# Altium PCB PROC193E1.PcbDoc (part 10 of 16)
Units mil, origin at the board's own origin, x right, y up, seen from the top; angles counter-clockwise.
Board outline 7700 x 2300 mil, 6 copper layers (Top Layer, GND 1, SIG 1, PWR, GND 2, Bottom Layer), stack 60.98 mil thick; 946 components, 667 nets, 9401 pads, 1730 vias.
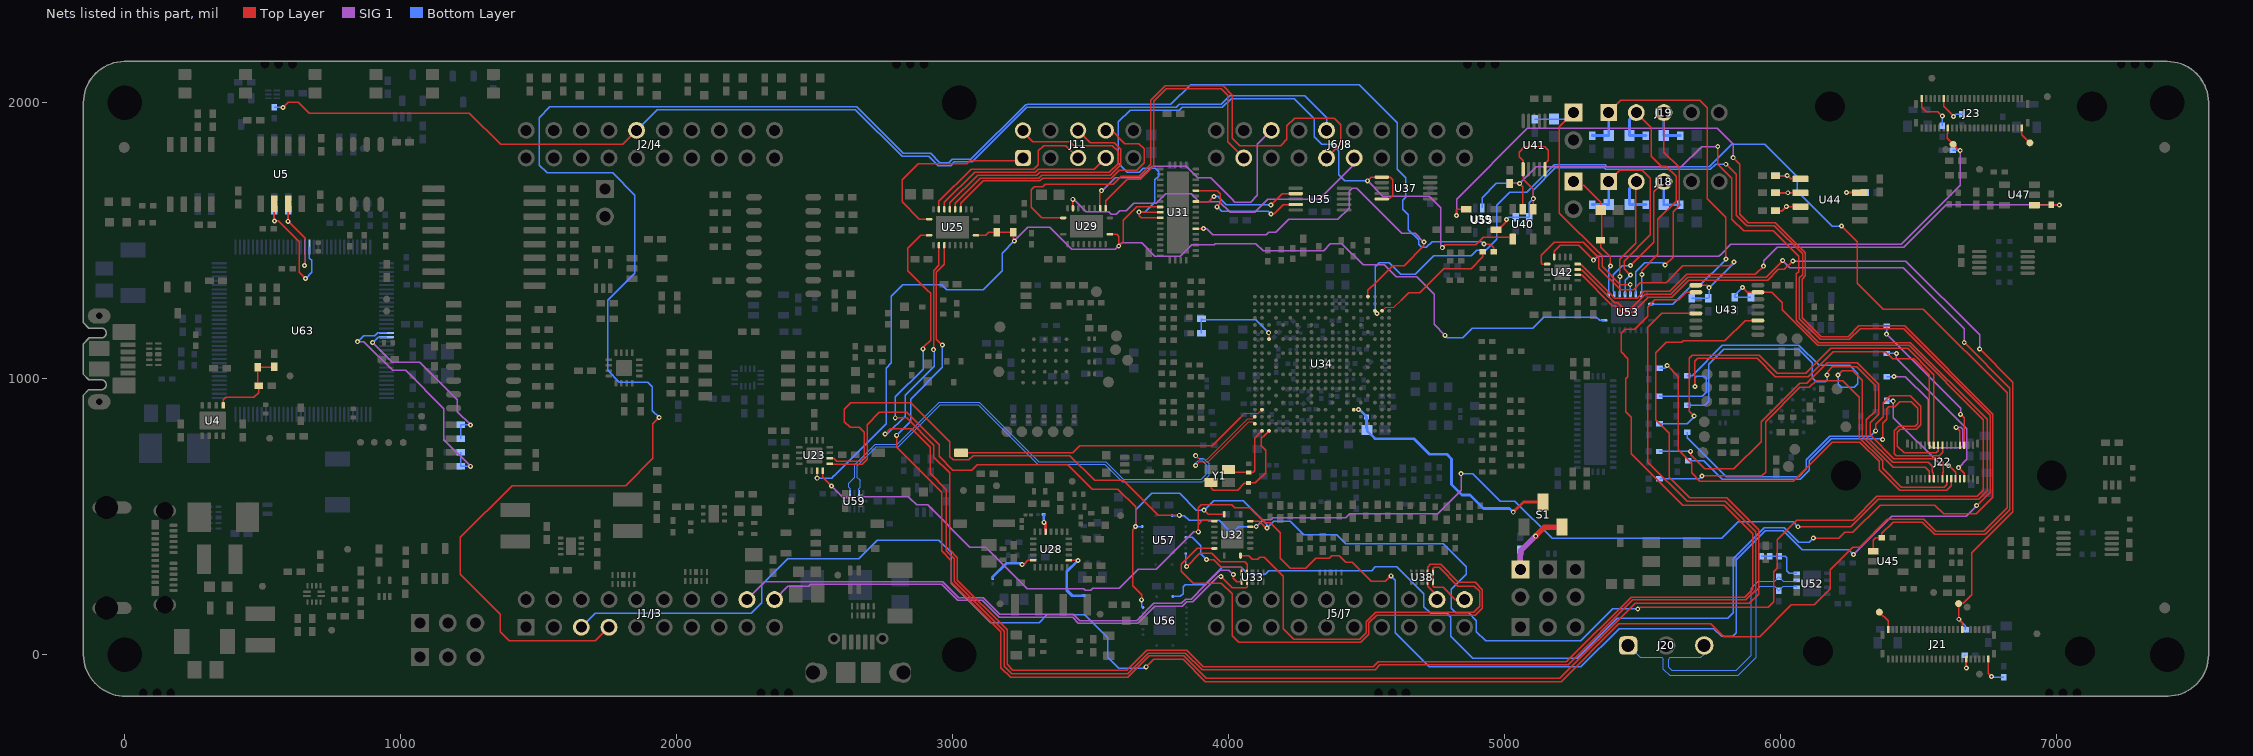
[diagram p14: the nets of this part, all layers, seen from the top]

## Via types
v1: diameter 18, hole 8, Top Layer to Bottom Layer, tented both sides, 1710 vias
v2: diameter 18, hole 8, Top Layer to Bottom Layer, tented top, 12 vias
v3: diameter 23.62, hole 11.81, Top Layer to Bottom Layer, tented both sides, 8 vias

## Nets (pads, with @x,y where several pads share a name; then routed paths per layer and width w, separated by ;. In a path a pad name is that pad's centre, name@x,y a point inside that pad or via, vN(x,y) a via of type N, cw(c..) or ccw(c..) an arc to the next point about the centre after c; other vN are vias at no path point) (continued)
AM261_UART3_RXD: J1/J3.3 U34.C18 | length 9757.5
  Top Layer w5.3: v1@3700.98,-43.56 3728.02,-16.52 3834.18,-16.52 3914.7,-97.04 5204.5,-97.04 5413.72,112.18 5746.9,112.18 5793.16,65.93 5923.9,65.93 6038.66,180.69 6121.12,180.69 6179.45,239.01 6179.45,308.99 6260.43,389.98 6284.37,389.98 6284.43,390.04 6285.17,390.04 6386.37,491.24 6517.78,491.24 6561.61,447.41 ; U34.C18@4529.52,1246.42 4536.77,1239.18 v1(4536.77,1236.43) ; v1(6220.27,1553.27) 6277.43,1496.1 6277.43,1346.74 6371.91,1252.26 6516.58,1252.26 6820.11,948.73 6820.11,532.79 6734.43,447.11 6561.93,447.11 6561.63,447.41
  Bottom Layer w5.3: J1/J3.3@1654.17,100 1704.25,150.07 2269.98,150.07 2308.09,188.19 2308.09,254.62 2402.06,348.58 2658.83,348.58 2725.97,415.72 2948.62,415.72 2951.81,412.53 2993.49,370.86 2994.67,369.67 2994.67,259.28 3137.05,116.89 3312.38,116.89 3341.09,145.6 3478.65,145.6 3562,62.25 3562,-8.66 3601.28,-47.93 3696.41,-47.93 v1(3700.78,-43.56) ; v1(4536.77,1236.43) 4536.77,1239.84 4530.72,1245.89 4530.72,1405.72 4546,1421 4581,1421 4623.53,1378.47 4675.47,1378.47 4742.37,1445.37 4877.82,1445.37 4897.53,1465.08 4931.26,1465.08 4971.37,1505.19 4971.37,1628.38 5018.5,1675.51 5080.2,1675.51 5179.33,1774.64 5364,1774.64 5369.72,1768.92 5740.92,1768.92 5821.55,1849.55 5940.96,1849.55 6059.24,1731.27 6059.24,1679.76 6185.73,1553.27 v1(6220.27,1553.27)
AM261_UART3_TXD: J1/J3.4 R172.1 | length 7527.5
  Top Layer w5.3: J1/J3.4@1754.17,100 1704.63,50.46 1393.79,50.46 1361.18,83.07 1361.18,146.72 1215.54,292.36 1215.54,425.29 1403.4,613.15 1814.26,613.15 1912.88,711.77 1912.88,836.52 v1(1936.3,859.93) ; v1(4925.1,1487.93) 4947,1487.93 4959.58,1475.35 4959.58,1461.04 R172.1@4959.95,1460.66
  Bottom Layer w5.3: v1(1936.3,859.93) 1911.69,884.54 1911.69,971.77 1895.44,988.02 1791.8,988.02 1749.41,1030.42 1749.41,1284.63 1848.05,1383.27 1848.05,1665.92 1767.49,1746.47 1529.89,1746.47 1501.97,1774.39 1500.76,1775.6 1500.76,1946.28 1540.47,1985.99 2651.41,1985.99 2820.61,1816.79 2919.91,1816.79 2953.34,1783.36 2985.96,1783.36 2998.43,1795.84 3065.89,1795.84 3263.79,1993.74 3269.46,1993.74 3269.76,1994.04 3790.19,1994.04 3862.3,2066.15 4472.11,2066.15 4610.2,1928.07 4610.2,1758.75 4641.15,1727.79 4641.15,1656.94 4630.24,1646.03 4630.24,1614.91 4650.95,1594.21 4650.95,1539.77 4687.33,1503.39 4687.33,1487.22 4698.76,1475.78 4714.94,1475.78 4736.33,1497.17 4915.65,1497.17 4924.89,1487.93 v1(4925.1,1487.93)
AM261_UART3_TXD_R: R172.2 U34.C19 | length 464.9
  Top Layer w3.94: U34.C19@4555.12,1246.42 4567.91,1259.22 4598.46,1259.22 4624.25,1285.01
  Top Layer w5.3: 4624.25,1285.01 4651.71,1312.47 4692.48,1312.47 4779.58,1399.57 4877.69,1399.57 4920.58,1442.47 R172.2@4920.58,1460.66
AM261_UART5_RXD: U31.27 U34.A17 | length 1326.9
  Top Layer w5.3: U31.27@3881.04,1543.92 3907.97,1543.92 v1(3908.26,1544.21) ; U34.A17@4503.93,1297.6 4503.93,1320.22 4532.14,1348.43 4593.86,1410.15 4635.64,1410.15 4706.85,1481.35 v1(4706.85,1495.3)
  SIG 1 w4.75: v1(3908.26,1544.21) 3919.5,1544.21 3941.52,1522.19 4136.2,1522.19 4144.42,1530.41 4169.24,1530.41 4216.59,1577.76 4395.17,1577.76 4435.97,1618.56 4435.97,1678.78 4447.4,1690.22 4464.23,1690.22 4627.25,1527.2 4674.96,1527.2 v1(4706.85,1495.3)
AM261_USB0_DRVVBUS: SW6.1 U34.U2 | length 1154.8
  Top Layer w3.94: 4043.66,860.5 4058.52,875.36 4107.28,875.36 U34.U2@4120.08,888.16
  Top Layer w5.3: SW6.1@3030.02,731.93 3435.18,731.93 3460.05,756.81 3939.74,756.81 3940.38,757.45 3940.61,757.45 4043.66,860.5
AM261_USB2.0_DM: U34.W1 U59.8 | length 1983.3
  Top Layer w4.2: v1(3879.98,685.43) 3893.38,698.83 3925.65,698.83 4013.45,786.63 4071.99,845.17 4086.29,845.17 U34.W1@4094.49,836.97
  Bottom Layer w4.2: U59.8@2628.07,584.08 2628.07,601.83 2623.63,606.26 2623.63,621.9 2639.3,637.57 2645.28,643.55 2645.28,689.12 2719.36,763.2 2799.34,763.2 2950.49,914.35 3095.5,914.35 3310.94,698.91 3554.05,698.91 3617.61,635.35 3900.16,635.35 3905.42,640.61 3919.06,654.25 3919.06,688.48 3903.77,703.77 3888.58,703.77 3881.73,696.92 3881.73,687.18 v1(3879.98,685.43)
AM261_USB2.0_DP: U34.V1 U59.10 | length 1983.8
  Top Layer w4.2: v1(3879.98,721.43) 3893.38,708.03 3921.84,708.03 4068.18,854.37 4086.29,854.37 U34.V1@4094.49,862.57
  Bottom Layer w4.2: U59.10@2659.56,584.08 2659.56,601.83 2664,606.26 2664,632.3 2658.73,637.57 2654.48,641.82 2654.48,685.31 2723.17,754 2803.15,754 2954.3,905.15 3091.69,905.15 3307.13,689.71 3550.24,689.71 3613.8,626.15 3903.97,626.15 3909.23,631.41 3928.26,650.44 3928.26,692.29 3907.58,712.97 3889.34,712.97 3880.88,721.43 v1(3879.98,721.43)
AM261_WARMRSTN: R325.1 R326.2 U34.G3 | length 339.7
  Top Layer w5.3: v1(4144.45,1166.96) 4145.67,1165.74 U34.G3@4145.67,1144.06
  Bottom Layer w5.3: R326.2@3900.83,1217.23 3903.64,1214.42 4097.14,1214.42 4144.45,1167.11 v1(4144.45,1166.96) ; R325.1@3901.01,1165.28 R326.2@3901.01,1217.06
AM261_XDS_I2C1_SCL: R381.2 R382.1 U63.82 | length 646.1
  SIG 1 w4.75: v1(898.28,1131.06) 969.75,1059.59 1068.02,1059.59 1204.06,923.55 1204.06,881.51 v1(1252.55,833.03)
  Bottom Layer w5.3: v1(898.28,1131.06) 917.96,1150.75 U63.82@948.65,1150.75 ; R381.2@1217.33,783.03 R382.1@1217.33,833.03 v1(1252.55,833.03)
AM261_XDS_I2C1_SDA: R379.1 R380.2 U63.81 | length 866.2
  SIG 1 w4.75: v1(843.5,1134.61) 866.26,1134.61 970.12,1030.75 1017.47,1030.75 1156.42,891.79 1156.42,779.54 v1(1252.93,683.03)
  Bottom Layer w5.3: v1(843.5,1134.61) 865.03,1156.14 905.95,1156.14 916.31,1166.5 U63.81@948.65,1166.5 ; R380.2@1217.33,733.03 R379.1@1217.33,683.03 v1(1252.93,683.03)
AM261_XTAL_XI: C88.2 U34.Y3 Y1.3 | length 407.1
  Top Layer w5.3: Y1.3@3935.33,614.43 3937.28,612.48 3937.28,602.85 3943.76,596.37 4032.37,596.37 4056.78,620.79 4069.55,620.79 C88.2@4071.47,622.7 4096.59,622.7 4133.79,659.91 4133.79,741.26 4118.29,756.75 4118.29,784.01 4130.13,795.85 U34.Y3@4145.67,811.38
AM261_XTAL_XO: C89.2 U34.Y2 Y1.1 | length 257.2
  Top Layer w5.3: Y1.1@3999.31,671.68 4010.35,660.64 C89.2@4072.36,660.64 4087.8,660.64 4093.97,666.81 4093.97,767.84 4093.97,785.28 U34.Y2@4120.08,811.38
BOOTMODE_XDS_I2C_SCL: R404.1 U5.3 U63.49 | length 359.4
  Top Layer w5.3: U5.3@591.82,1634.52 v1(591.82,1570.46) 653.63,1508.65 653.63,1413.16 v1(650.96,1410.49)
  Bottom Layer w5.3: v1(591.82,1570.46) R404.1@591.82,1610.89 ; v1(650.96,1410.49) 653.63,1413.16 653.63,1477.27 U63.49@653.37,1477.52
BOOTMODE_XDS_I2C_SDA: R406.1 U5.2 U63.50 | length 492.4
  Top Layer w5.3: U5.2@541.82,1634.52 541.82,1572.19 v1(541.97,1572.04) 556.6,1572.04 631.38,1497.26 631.38,1386.58 v1(654.75,1363.22)
  Bottom Layer w5.3: R406.1@541.82,1610.89 541.82,1572.19 v1(541.97,1572.04) ; v1(654.75,1363.22) 677.03,1385.5 677.03,1429.33 669.12,1437.24 U63.50@669.12,1477.52
BP_BO_MUX_EN: R90.1 R91.2 U23.7 U25.10 U29.10 U31.8 U53.10 | length 4407.9
  Top Layer w5.3: v1(2508.54,639.98) U23.7@2508.54,667.03 ; U25.10@3083.62,1519.54 3118.91,1519.54 3130.41,1531.05 R90.1@3160.08,1531.05 R91.2@3219.24,1531.05 3219.24,1506.56 3223.02,1502.78 v1(3223.02,1499.34) ; U29.10@3569.3,1523.67 3593.38,1523.67 3601.28,1515.77 v1(3601.28,1481.55) 3616.99,1497.26 3616.99,1573.56 3666.61,1623.18 3683.17,1623.18 3683.69,1622.66 U31.8@3751.12,1622.66
  SIG 1 w4.75: v1(3223.02,1499.34) 3272.25,1548.57 3351.96,1548.57 3430.91,1469.62 3589.35,1469.62 v1(3601.28,1481.55) 3611.81,1492.08 3684.93,1492.08 3732.58,1444.42 3824.52,1444.42 3865.4,1485.3 3947.22,1485.3 3951.79,1489.87 4098.55,1489.87 4124.04,1464.38 4343.18,1464.38 4368.33,1489.52 4409.94,1489.52 4486.89,1412.58 4563.75,1412.58 4606.32,1370.01 4680.3,1370.01 4743.68,1306.64 4743.68,1196.81 v1(4782.87,1157.62)
  Bottom Layer w5.3: v1(2508.54,639.98) 2560.85,639.98 2569.12,648.25 2569.68,648.25 2580.61,659.18 2580.61,659.73 2758.27,837.39 2758.27,1038.71 2776.95,1057.39 2776.95,1299.95 2817.81,1340.81 2960.08,1340.81 2977.79,1323.1 3111.03,1323.1 3179.44,1391.51 3179.44,1455.77 v1(3223.02,1499.34) ; v1(4782.87,1157.62) 4783.35,1157.62 4792.32,1148.64 4846.95,1148.64 4882.18,1183.88 5101.47,1183.88 5141.21,1223.61 5331.56,1223.61 5343.3,1211.87 U53.10@5360.84,1211.87
BP_BO_MUX_EN_N: R266.2 R267.1 U23.9 U32.1 U32.15 U43.15 U56.15 U57.15 | length 7424.7
  Top Layer w5.3: U23.9@2553.81,692.62 2555.41,691.02 2672.18,691.02 2689.46,708.31 2689.46,834.12 2733.55,878.2 2833.62,878.2 2950.32,761.5 2950.32,718.96 3000.7,668.58 3068.87,668.58 3088.78,688.48 3417.09,688.48 3505.21,600.36 3598.32,600.36 3662.05,536.64 v1(3662.05,464.41) 3651.54,453.9 3651.54,250.96 3684.05,218.45 v1(3684.05,199.17) ; v1(3910.51,523.8) 3925.01,509.3 U32.1@3983.28,509.3 ; U32.15@4077.76,483.71 4078.37,484.31 4110.52,484.31 4135.71,459.11 v1(4138.02,459.11) ; v1(5481.73,166.42) 5485.16,166.42 5490.42,171.68 5953.77,171.68 5975,192.91 5975,301.34 5987.2,313.54 5987.2,416.73 6057.87,487.4 6261.88,487.4 6348.25,573.77 6711.08,573.77 6734.1,596.79 6734.1,852.01 6465.06,1121.05 6133.73,1121.05 6004.36,1250.42 6004.36,1276.22 5967.11,1313.47 U43.15@5916.65,1313.47 5879.19,1313.47 v1(5861.48,1331.19)
  Bottom Layer w5.3: v1(3684.05,199.17) 3684.05,176.75 U56.15@3689.17,171.63 ; U57.15@3686.31,464.84 3686.09,464.63 3662.26,464.63 v1(3662.05,464.41) 3662.05,524.95 3721.7,584.6 3821.67,584.6 3882.46,523.8 v1(3910.51,523.8) 3945.7,559 4051.91,559 4138.02,472.89 v1(4138.02,459.11) 4162.69,483.78 4222.22,483.78 4271,435 4392,435 4424.43,402.57 4777.43,402.57 4860.78,319.22 4860.78,292.49 4806,237.71 4806,168 4822,152 4869,152 4897,124 4897,84 4930.41,50.59 5275.29,50.59 5391.12,166.42 v1(5481.73,166.42) ; v1(5861.48,1331.19) 5833.71,1303.42 R267.1@5833.71,1295.76 R266.2@5892.01,1295.76
BP_MCAN0_RX: U31.34 U35.9 | length 455.5
  Top Layer w5.3: U31.34@3881.04,1681.72 3958.46,1681.72 3969.66,1670.52 3969.66,1635.22 v1(3957.53,1623.1) ; v1(4153.42,1597.1) 4155.13,1598.82 4165.08,1598.82 4197.59,1631.32 U35.9@4242.38,1631.32
  Bottom Layer w5.3: v1(3957.53,1623.1) 3973.87,1606.76 4143.77,1606.76 v1(4153.42,1597.1)
BP_MCAN0_TX: U31.32 U35.7 | length 398.8
  Top Layer w5.3: U31.32@3881.04,1642.35 3927.35,1642.35 v1(3946,1661) ; v1(4152.12,1629.94) 4152.98,1629.94 4193.74,1670.69 U35.7@4242.38,1670.69
  Bottom Layer w5.3: v1(3946,1661) 3946.13,1660.87 3959.24,1660.87 3990.16,1629.94 v1(4152.12,1629.94)
BP_MUX_SW0_EXOR_SW1: U31.9 U31.10 U37.1 U37.5 U40.4 | length 2754.4
  Top Layer w5.3: U31.10@3751.12,1583.29 3683,1583.29 3675.08,1591.21 v1(3675.08,1603.66) 3675.76,1602.98 U31.9@3751.12,1602.98 ; v1(4502.64,1717.34) 4515.67,1730.37 4554.19,1730.37 U37.1@4554.27,1730.45 ; U37.5@4554.27,1651.71 4582.17,1651.71 4593.77,1663.32 4593.77,1721.87 4585.01,1730.63 U37.1@4554.44,1730.63 ; v1(4773.49,1475.03) 4784.22,1485.76 4895.33,1485.76 4922.72,1513.16 5021.2,1513.16 U40.4@5028.41,1505.94
  SIG 1 w4.75: v1(4502.64,1717.34) 4558.55,1661.43 4726.57,1661.43 4768.38,1619.62 4768.38,1483.72 4773.49,1478.61 v1(4773.49,1475.03)
  Bottom Layer w5.3: v1(3675.08,1603.66) 3695.07,1603.66 3731.79,1640.38 3731.79,1720.78 3745.4,1734.39 3745.4,1750.56 3733.96,1762 3689.15,1762 3676.37,1749.22 3631.83,1749.22 3600.01,1781.04 3600.01,1930.51 3642.33,1972.84 3821.07,1972.84 3831.67,1983.44 3977.17,1983.44 4008.38,2014.65 4237.98,2014.65 4309.65,1942.98 4309.65,1876.5 4336.15,1850 4375.38,1850 4398.57,1826.81 4398.57,1739.09 4420.32,1717.34 v1(4502.64,1717.34)
BP_MUX_SW0_N_AND_SW1: U39.4 U56.1 | length 6900.3
  Top Layer w5.3: v1(4825.38,1591.58) 4824.35,1592.61 4824.35,1611.18 4828.21,1615.04 U39.4@4860.29,1615.04 ; v1(5827.65,1801.13) 5851.89,1776.9 5851.89,1595.73 5882.1,1565.52 5980.72,1565.52 6089.15,1457.09 6089.15,1373.42 6077.24,1361.51 6077.24,1222.01 6146.34,1152.91 6244.61,1152.91 6283.15,1191.45 6449.33,1191.45 6768.61,872.17 6768.61,571.23 6708.46,511.08 6589.77,511.08 6558.12,542.74 6360.92,542.74 6261.54,443.36 6230.91,443.36 6210.67,423.12 v1(6117.93,423.12)
  SIG 1 w4.75: v1(4825.38,1591.58) 4825.38,1651.38 5082,1908 5770,1908 5827.65,1850.35 v1(5827.65,1801.13)
  Bottom Layer w5.3: U56.1@3797.44,211.39 3824.47,211.39 3834.75,221.66 3834.75,247.34 3841.91,254.51 3913.17,254.51 3975.96,317.3 4044.55,317.3 4070.45,291.41 4131.55,291.41 4145.14,305 4518.04,305 4531.16,318.13 4609.15,318.13 4706.85,220.42 4706.85,173.8 4730.82,149.83 4790.59,149.83 4804.27,136.15 4804.27,67.41 4883.83,-12.15 5263.21,-12.15 5407.85,132.5 5807.88,132.5 5827.3,151.91 5827.3,253.67 5827.9,254.27 5827.9,348.31 5940.33,460.74 6012.98,460.74 6065.06,408.66 6103.47,408.66 v1(6117.93,423.12)
BP_MUX_SW_S0: R175.2 R303.1 U23.10 U32.14 U40.2 U55.2 U57.1 | length 8116.8
  Top Layer w5.3: U23.10@2553.81,712.31 2554.21,711.91 2569.43,711.91 2579.46,701.89 2667.1,701.89 2678.38,713.17 2678.38,806.68 2660.93,824.14 2627.74,824.14 2606.67,845.21 2606.67,890.19 2630.11,913.64 2847.61,913.64 2989.78,771.47 2989.78,718.47 3001.8,706.45 3058.53,706.45 3073.52,721.43 3424.2,721.43 3513.48,632.15 3615.62,632.15 3615.75,632.02 3617.98,632.02 3744.68,505.32 v1(3820.64,505.32) ; U32.14@4077.76,464.02 4078.15,464.4 4099.12,464.4 v1(4099.5,464.79) ; R175.2@5017.69,1707.81 v1(5053.84,1707.81) 5065.82,1695.82 U40.2@5065.82,1614.21 ; v1(5771.53,1841.58) 5771.53,1777.57 5822.54,1726.56 5822.54,1578.54 5864.86,1536.21 5973.12,1536.21 6064.77,1444.56 6064.77,1388.19 6056.64,1380.07 6056.64,1212.7 6138,1131.35 6434.84,1131.35 6469.33,1131.35 6747.87,852.81 6747.87,594.34 6717,563.47 6352.52,563.47 6253.01,463.96 v1(6062.04,463.96)
  SIG 1 w4.75: v1(4099.5,464.79) 4124.09,489.39 4151.14,489.39 4158.57,496.82 4424.28,496.82 4438.34,510.88 4756.88,510.88 4841.82,595.82 v1(4841.82,656.33)
  SIG 1 w5.3: v1(5053.84,1707.81) 5113.83,1767.81 5639.45,1767.81 5713.23,1841.58 v1(5771.53,1841.58)
  Bottom Layer w5.3: U57.1@3794.57,504.6 v1@3819.93,504.6 ; v1(3820.64,505.32) v1@3819.93,504.6 ; v1(4099.5,464.79) 4036.12,464.79 4021.16,449.83 4002.29,449.83 3964.85,487.27 3856.01,487.27 3838.67,504.6 v1@3819.93,504.6 ; v1(4841.82,656.33) 4884.57,656.33 4983.93,556.97 5036.48,556.97 5171.45,422 5785.75,422 5845.09,481.34 6044.65,481.34 v1(6062.04,463.96) ; U55.2@4918.17,1619.01 4918.17,1656.11 4969.87,1707.81 R303.1@5017.69,1707.81 v1(5053.84,1707.81)
BP_MUX_SW_S1: R301.2 R302.1 U23.8 U32.2 U39.1 U40.1 U41.1 U41.5 | length 8942.2
  Top Layer w5.3: U23.8@2528.22,667.03 2528.22,643.98 v1(2560.77,611.42) ; v1(3889.58,445.68) 3889.37,445.9 3889.02,445.9 3889.02,471.66 ; U32.2@3947.84,483.71 3926.34,483.71 3922.99,487.06 3904.42,487.06 3889.02,471.66 ; v1(4587.26,286.14) 4567.01,265.88 4516.1,265.88 4446.7,335.28 4423.75,335.28 4412.34,346.7 4406.45,352.64 ccw(c4392.59,338.88) 4406.31,352.78 4400.68,358.41 4373.36,358.41 4364.42,349.47 4315.28,349.47 4278.62,312.81 4222.37,312.81 4185.93,349.25 4185.93,442.24 4150.51,477.66 4145.86,477.66 4145.75,477.76 4131.63,477.76 4076.2,533.19 4021.17,533.19 4010.37,543.99 3900.87,543.99 3889.02,532.14 3889.02,471.66 ; U39.1@4968.56,1540.23 4976.44,1540.23 5006,1569.79 v1(5006,1577.64) ; U40.1@5103.22,1614.21 v1(5103.22,1652.61) 5103.22,1686.04 5066.55,1722.71 5066.55,1789.84 5062.91,1793.48 5051.67,1804.72 5051.67,1821.28 5070.64,1840.25 5145.15,1840.25 5157.02,1828.39 5157.02,1791.4 5145.29,1779.68 U41.5@5145.29,1759.01 ; v1(5800.66,1777.31) 5802.2,1777.31 5838.29,1741.22 5838.29,1593.35 5875.27,1556.36 5876.69,1556.36 5877.83,1555.22 5976.46,1555.22 6078.85,1452.83 6078.85,1377.68 6066.94,1365.78 6066.94,1217.75 6142.07,1142.61 6248.88,1142.61 6287.41,1181.15 6445.06,1181.15 6758.31,867.91 6758.31,588.54 6710.4,540.63 v1(6709.9,540.63)
  SIG 1 w4.75: 2846.57,565.57 2869.15,543 2908.78,543 3062.03,389.75 3119.65,389.75 3270.39,239.01 3474.46,239.01 3479.7,233.78 3499.72,233.78 3507.52,241.58 3602.57,241.58 3671.58,310.59 3737.3,310.59 3872.35,445.64 3889.54,445.64 v1(3889.58,445.68) ; v1(6263.22,363.2) 6401.57,501.54 6671.31,501.54 6709.9,540.13 v1(6709.9,540.63)
  SIG 1 w5.3: v1(2560.77,611.42) 2599.2,573 2839.15,573 2846.57,565.57
  Bottom Layer w5.3: v1(4587.26,286.14) 4603.05,270.34 4603.05,80.62 4726.72,-43.05 5276.01,-43.05 5414.25,95.19 5757.74,95.19 5786.2,66.73 5825.94,66.73 5838.2,79 5838.2,344.05 5943.89,449.74 6008.84,449.74 6078.51,380.06 6246.36,380.06 v1(6263.22,363.2) ; v1(5006,1577.64) 5013.68,1585.32 R302.1@5039.74,1585.32 R301.2@5088.74,1585.32 5088.74,1638.13 v1(5103.22,1652.61) 5103.22,1683.97 5183.59,1764.34 5359.73,1764.34 5365.59,1758.48 5745.05,1758.48 5763.88,1777.31 v1(5800.66,1777.31)
BP_PORZ: J2/J4.16 J6/J8.56 R408.2 | length 4202.6
  Top Layer w5.3: v1(573.46,1983.42) 591.58,2001.54 628.24,2001.54 667.47,1962.31 1215.57,1962.31 1231.21,1962.31 1248.51,1962.31 1361.26,1849.56 1803.74,1849.56 J2/J4.16@1854.17,1900
  Bottom Layer w5.3: R408.2@541.97,1983.78 573.11,1983.78 v1(573.46,1983.42) ; J2/J4.16@1854.17,1900 1929.87,1975.69 2647.15,1975.69 2816.35,1806.49 2913.29,1806.49 2947.7,1772.09 2992.22,1772.09 3005.67,1785.54 3070.16,1785.54 3268.06,1983.44 3809.91,1983.44 3820.52,1994.04 3973.2,1994.04 4004.11,2024.95 4274.88,2024.95 4354.17,1945.66 J6/J8.56@4354.17,1900
BP_SPI2_CS0: J6/J8.58 U29.13 | length 987.7
  Top Layer w5.3: U29.13@3533.07,1628.97 3533.07,1618.95 U29.13@3533.87,1618.16 ; U29.13@3533.06,1628.98 3533.06,1672.74 3538.46,1678.14 v1(3538.46,1681.57)
  SIG 1 w4.75: v1(3538.46,1681.57) 3541.49,1681.57 3588.17,1728.25 3681.07,1728.25 3722.96,1770.13 3845.87,1770.13 3887.37,1728.63 3933.97,1728.63 4010.84,1651.76 4010.84,1651.7 4022.11,1640.42 4022.17,1640.42 4023.02,1640.42 4023.25,1640.19 4057.05,1640.19 4057.28,1640.42 4078.74,1640.42 4103.98,1665.65 4103.98,1849.81 J6/J8.58@4154.17,1900
CAN_STB: R257.1 R264.2 R265.1 U52.8 | length 181.5
  Bottom Layer w5.3: R265.1@5928.76,356.28 R264.2@5960.46,356.28 R257.1@5994.28,356.28 6016.9,356.28 6022.29,350.89 6022.29,304.28 6030.47,296.1 U52.8@6057.99,296.1
CANA_N: J20.1 R261.2 U52.6 | length 967.9
  Bottom Layer w3.8: J20.1@5446.96,33.86 5490.35,-9.53 5568.65,-9.53 5574.94,-15.82 5574.94,-52.72 5597.07,-74.85 5845.72,-74.85 5910.85,-9.72 5910.85,232.82 5926.34,248.31 5977.51,248.31 R261.2@5993.11,232.71 6008.71,248.31 6054.59,248.31 U52.6@6057.99,244.92
CANA_P: J20.3 R262.2 U52.7 | length 955.8
  Bottom Layer w3.8: J20.3@5722.55,33.86 5722.55,2.58 5710.44,-9.53 5600.34,-9.53 5593.74,-16.13 5593.74,-44.93 5604.86,-56.05 5837.93,-56.05 5892.05,-1.93 5892.05,240.61 5918.55,267.11 5977.51,267.11 R262.2@5993.11,282.71 6008.71,267.11 6054.59,267.11 U52.7@6057.99,270.51
CPSW/ICSS_BRD_CONN_DET1: J21.36 R234.1 TP50.1 U42.2 | length 2961.2
  Top Layer w5.3: U42.2@5263.64,1376.37 5263.91,1376.1 5279.38,1376.1 5390.04,1265.44 5399.59,1265.44 5423.63,1241.4 5465.89,1241.4 5520.44,1295.95 5605.46,1295.95 5666.98,1357.46 5952.9,1357.46 5991.49,1396.06 6013.2,1396.06 v1(6043.54,1426.39) ; J21.36@6656.78,91.39 6656.78,116.9 6644.15,129.53 TP50.1@6644.15,185.3 6645.7,186.86 6660.91,186.86 6679.45,205.39 6692.05,218 6692.05,369.75 6840.71,518.41 6840.71,988.23 v1(6720.46,1108.48)
  SIG 1 w5.3: v1(6043.54,1426.39) 6452.86,1426.39 6720.46,1158.8 v1(6720.46,1108.48)
  Bottom Layer w5.3: v1(6644.87,128.8) 6668.37,105.31 6668.37,91.42 R234.1@6669.17,90.62
CPSW/ICSS_BRD_CONN_DET2: J23.36 R237.1 TP49.1 U42.8 | length 1894.5
  Top Layer w5.3: U42.8@5178.99,1441.33 5178.99,1462.99 5200,1484 5267.49,1484 5321.53,1429.96 v1(5321.53,1429.88) ; J23.36@6605.69,1908.44 6605.69,1890.55 6602.79,1887.65 6602.79,1870.91 TP49.1@6624.15,1849.55 6646.7,1827 v1(6650,1827)
  SIG 1 w4.75: v1(5321.53,1429.88) 5335.99,1444.34 5775.64,1444.34 5779.56,1448.26 5779.76,1448.26 5818.51,1487.01 6435.69,1487.01 6650,1701.31 v1(6650,1827)
  Bottom Layer w5.3: R237.1@6622.33,1828.78 6648.22,1828.78 v1(6650,1827)
DAC_EXT_VREF: C157.1 J12.1 S1.3 | length 312.8
  Top Layer w20: v1(5111.94,429.89) 5111.94,431.17 5143.7,462.93 S1.3@5207.56,462.93
  SIG 1 w20: J12.1@5056.57,309.25 5056.57,375.81 5110.65,429.89 v1(5111.94,429.89)
  Bottom Layer w20: J12.1@5056.57,309.25 5056.57,365.5 5058.1,363.98
DAC_OUT/ADC0_AIN6: J1/J3.29 U33.1 U33.10 U57.4 | length 2293.6
  Top Layer w5.3: v1(3919.71,344.91) 3944.99,344.91 3971.9,318.01 4041.65,318.01 4046.55,313.1 U33.10@4046.55,297.78 U33.1@4046.55,264.9 4029.31,264.9 4016.33,277.88 v1(4016.33,291.12)
  SIG 1 w4.75: J1/J3.29@2254.17,200 2318.64,264.46 2964.06,264.46 3021.37,207.15 3110.23,207.15 3169.74,147.64 3435.99,147.64 3459.5,124.12 3665.83,124.12 3727.65,185.94 3827.94,185.94 3843.8,201.8 3864.13,201.8 3889.22,226.88 3889.22,228.84 3967.52,307.14 4000.31,307.14 v1(4016.33,291.12)
  Bottom Layer w5.3: U57.4@3843.79,425.47 3867.7,425.47 3898.47,394.7 3898.47,366.16 v1(3919.71,344.91)
DAC_OUT/ADC1_AIN6: J1/J3.30 U33.2 U33.9 U57.7 | length 2268
  Top Layer w5.3: v1(3847.27,319.45) 3895.14,367.32 3937.35,367.32 3968.17,336.5 4058.52,336.5 4066.23,328.79 U33.9@4066.23,297.78 U33.2@4066.23,264.9 4066.23,245.45 4063.13,242.34 4012.48,242.34 v1(3970.96,283.87)
  SIG 1 w4.75: J1/J3.30@2354.17,200 2402.35,248.17 2478.86,248.17 2485.4,254.71 2960.02,254.71 3017.33,197.4 3106.19,197.4 3167.89,135.7 3433.74,135.7 3455.07,114.38 3669.87,114.38 3731.69,176.19 3831.98,176.19 3847.84,192.05 3870.21,192.05 3962.02,283.87 v1(3970.96,283.87)
  Bottom Layer w5.3: U57.7@3843.79,366.41 3843.79,328.91 3844.84,327.85 3844.84,321.88 v1(3847.27,319.45)
DAC_OUT/PR1_PRU0_GPIO6/ADC2_AIN3: J5/J7.69 U32.7 U38.2 U38.9 | length 1969.9
  Top Layer w5.3: U32.7@3947.84,385.28 3885.71,385.28 3879.3,378.87 3879.08,378.87 3827.75,327.54 3827.75,303.43 3871.61,259.56 3972.85,259.56 4011.9,220.5 4011.9,69.18 4035.16,45.92 4474.01,45.92 4478.13,45.92 4507.42,75.21 4507.42,115.85 4535.69,144.13 4893.64,144.13 4919.01,169.49 4919.01,236.48 4892.25,263.24 4832.15,263.24 4767.1,328.29 4730.66,328.29 4719.99,317.63 U38.2@4719.99,297.78 U38.9@4719.99,264.9 4719.99,249.13 4754.17,214.96 J5/J7.69@4754.17,200
DAC_OUT/PR1_PRU1_GPIO5/ADC2_AIN6: J5/J7.70 U32.9 U38.1 U38.10 | length 1640.3
  Top Layer w5.3: U32.9@4042.33,359.69 4071.8,359.69 4085.13,346.36 4104.99,346.36 4112.29,353.66 4128.75,353.66 4197.9,284.52 4197.9,93.66 4235.34,56.22 4473.86,56.22 4497.12,79.47 4497.12,120.12 4531.91,154.91 4887.29,154.91 4908.37,175.99 4908.37,229.35 4888.74,248.98 4829.02,248.98 4761.65,316.35 4743.98,316.35 4739.68,312.05 U38.1@4739.68,297.78 U38.10@4739.68,264.9 4739.68,249.66 4745.04,244.3 4776.52,244.3 4820.83,200 J5/J7.70@4854.17,200
DAC_VREF: C168.1 C171.1 S1.2 U34.U15 | length 939.1
  Top Layer w5.3: U34.U15@4452.75,888.16 4453.04,888.45 4470.01,888.45 v1(4470.3,888.73)
  Top Layer w10: v1(5030.62,516.78) 5067.33,553.48 S1.2@5138.66,553.48
  Bottom Layer w10: v1(4470.3,888.73) 4471.83,887.2 4475.14,887.2 4494.69,867.66 4494.69,864.8 4497.95,861.53 C171.1@4498.74,861.53 4498.74,822.22 4501.23,819.73 C168.1@4501.23,814.75 4501.23,810.9 4529.13,783 4670.27,783 4726.77,726.51 4790.22,726.51 4807.34,709.38 4807.34,617.53 4845.43,579.44 4873.26,579.44 4922.72,529.98 5017.42,529.98 v1(5030.62,516.78)
EEPROM_A0: R200.2 R260.2 U44.1 | length 138
  Top Layer w5.3: R200.2@5981.07,1736.2 6022.36,1736.2 v1(6023.05,1736.89) 6035.89,1724.05 U44.1@6071.17,1724.05
  Bottom Layer w5.3: R260.2@5981.07,1736.2 6022.36,1736.2 v1(6023.05,1736.89)
EEPROM_A1: R202.2 R259.2 U44.2 | length 134.3
  Top Layer w5.3: R202.2@5981.07,1674.05 v1(6025.32,1674.05) U44.2@6071.17,1674.05
  Bottom Layer w5.3: R259.2@5981.07,1674.05 v1(6025.32,1674.05)
EEPROM_A2: R201.2 R258.2 U44.3 | length 142.5
  Top Layer w5.3: R201.2@5981.07,1609.41 6006.15,1609.41 6019.81,1623.07 v1(6019.81,1624.58) ; v1@6020.56,1623.83 6070.95,1623.83 U44.3@6071.17,1624.05
  Bottom Layer w5.3: R258.2@5981.07,1609.41 6006.15,1609.41 6019.81,1623.07 v1(6019.81,1624.58)
EEPROM_WP: R246.1 U44.7 | length 115.3
  Top Layer w5.3: v1(6237.78,1675.15) 6238.89,1674.05 U44.7@6285.74,1674.05
  Bottom Layer w5.3: v1(6237.78,1675.15) 6237.93,1675 R246.1@6304.65,1675
EPWM5_B: J6/J8.79 U29.12 | length 1035.2
  Top Layer w5.3: U29.12@3553.55,1618.16 3553.55,1644.97 3631.99,1723.41 3679.2,1723.41 3727.56,1771.78 3727.56,2004.71 3774.13,2051.27 3971.87,2051.27 3995.33,2027.81 3995.33,1858.84 J6/J8.79@4054.17,1800
EPWM7_A: J6/J8.76 U29.20 | length 2014.2
  Top Layer w5.3: U29.20@3400.01,1582.73 3322.75,1582.73 3283.86,1621.62 3283.86,1685.86 3294.52,1696.52 3325.3,1696.52 3334.17,1705.39 3582.24,1705.39 3582.75,1705.9 3582.96,1705.9 3585.21,1708.15 3611.08,1734.01 3674.81,1734.01 3717.26,1776.47 3717.26,2008.97 3717.44,2009.15 3717.44,2009.57 3769.74,2061.87 3978.99,2061.87 4013.14,2027.73 4013.14,1871.65 4040,1844.78 4187.91,1844.78 4210.46,1867.33 4210.46,1916.62 4238.34,1944.49 4382.14,1944.49 4405.81,1920.83 4405.81,1851.64 J6/J8.76@4354.17,1800
EPWM7_B: J6/J8.75 U29.18 | length 1228
  Top Layer w5.3: v1(3434.8,1650.39) 3435.48,1649.71 U29.18@3435.48,1618.19
  SIG 1 w4.75: v1(3434.8,1650.39) 3438.39,1650.39 3443.13,1645.64 3443.36,1645.64 3484,1605 3565,1605 3574,1596 3593,1596 3605.74,1608.74 3629.04,1608.74 3656.44,1636.14 3736.27,1636.14 3771.32,1671.2 3863.66,1671.2 3892.51,1642.35 3966.09,1642.35 4004.77,1603.66 4094.06,1603.66 4141.41,1651.01 4327.65,1651.01 4454.17,1777.53 J6/J8.75@4454.17,1800
EQEP0_A: C153.1 J19.1 R299.1 U53.20 | length 1445.8
  Top Layer w5.3: J19.1@5376.52,1964.55 5420.76,2008.8 5707.03,2008.8 5732.87,1982.95 5732.87,1652.02 5799.88,1585.01 5799.88,1435.47 v1(5801.75,1433.61)
  Bottom Layer w5.3: U53.20@5530.13,1270.93 5609.04,1270.93 5671.33,1333.22 5701.35,1333.22 v1(5801.75,1433.61)
  Bottom Layer w10: R299.1@5316.52,1881.05 C153.1@5376.52,1881.05 J19.1@5376.52,1964.55
EQEP0_B: C151.1 J19.2 R297.1 U53.18 | length 934.1
  Top Layer w5.3: J19.2@5476.52,1964.55 5531.04,1910.02 5531.04,1806.77 5567.61,1770.21 5583.67,1770.21 5620.84,1733.04 5620.84,1643.37 5554.94,1577.48 5554.94,1546.26 5554.94,1451.51 5495.62,1392.19 5495.62,1379.09 v1(5496.36,1378.35)
  Bottom Layer w5.3: U53.18@5494.7,1306.36 5495.49,1307.16 5495.49,1377.47 v1(5496.36,1378.35)
  Bottom Layer w10: J19.2@5476.52,1964.55 5451.52,1939.55 C151.1@5451.52,1881.04 R297.1@5511.52,1881.04
EQEP0_INDEX: C149.1 J19.3 R281.1 U53.17 | length 944
  Top Layer w5.3: J19.3@5576.52,1964.55 5576.52,1821.48 5631.44,1766.56 5631.44,1627.76 5609.46,1605.79 5609.46,1441.2 v1(5581.02,1412.76)
  Bottom Layer w5.3: U53.17@5475.01,1306.36 5475.01,1388.68 5506.8,1420.47 5571.57,1420.47 5579.27,1412.76 v1(5581.02,1412.76)
  Bottom Layer w10: J19.3@5576.52,1964.55 5575.69,1963.72 C149.1@5575.69,1881.04 R281.1@5635.69,1881.04
EQEP0_STROBE: C155.1 J16.1 R300.1 U53.16 | length 958.3
  Top Layer w5.3: J16.1@5248.63,1964.55 5197.86,1913.78 5197.86,1599.84 5352.59,1445.11 5352.59,1406.97 5418.17,1341.39 v1@5454.17,1341.39
  Bottom Layer w5.3: R300.1@5107.66,1939.9 5177.38,1939.9 C155.1@5178.34,1940.86 5224.94,1940.86 J16.1@5248.63,1964.55 ; v1(5454.54,1341.76) 5455.29,1341.02 U53.16@5455.33,1306.36 U53.16@5455.33,1306.36
EQEP1_A: C152.1 J18.1 R298.1 U53.15 | length 800.4
  Top Layer w5.3: J18.1@5376.52,1714.55 5417.22,1755.25 5459.18,1755.25 5459.52,1755.58 5498.47,1755.58 5527.75,1726.31 5527.75,1521.5 5432.73,1426.48 5432.73,1398.27 v1(5455,1376)
  Bottom Layer w5.3: U53.15@5435.64,1306.36 5435.64,1356.64 v1(5455,1376)
  Bottom Layer w10: R298.1@5316.52,1631.05 C152.1@5376.52,1631.05 J18.1@5376.52,1714.55
EQEP1_B: C150.1 J18.2 R296.1 U53.14 | length 587.3
  Top Layer w5.3: v1(5416.82,1370.73) 5416.82,1433.51 5474.54,1491.22 5474.54,1712.57 J18.2@5476.52,1714.55
  Bottom Layer w5.3: U53.14@5415.96,1306.36 5415.73,1306.59 5415.73,1369.63 v1(5416.82,1370.73)
  Bottom Layer w10: J18.2@5476.52,1714.55 5451.52,1689.55 C150.1@5451.52,1631.04 R296.1@5511.52,1631.04
EQEP1_INDEX: C148.1 J18.3 R280.1 U53.13 | length 646.7
  Top Layer w5.3: v1(5455,1410) 5540,1495 5540,1550.42 5540,1678.03 J18.3@5576.52,1714.55
  Bottom Layer w5.3: U53.13@5396.27,1306.36 5396.27,1314.57 5392.89,1317.95 5392.89,1377.19 5425.7,1410 v1(5455,1410)
  Bottom Layer w10: J18.3@5576.52,1714.55 5575.69,1713.72 C148.1@5575.69,1631.04 R280.1@5635.69,1631.04
EQEP1_STROBE: C110.1 J15.1 R192.1 U53.12 | length 485.1
  Top Layer w5.3: J15.1@5248.63,1714.55 5261.14,1702.04 5285.96,1702.04 5347.44,1640.56 C110.1@5347.44,1611.36 5351.54,1607.25 5351.54,1505.82 R192.1@5347.07,1501.35 5347.27,1501.15 5347.27,1477.27 5382.64,1441.9 v1(5382.64,1408.84)
  Bottom Layer w5.3: U53.12@5376.59,1306.36 5375.8,1307.16 5375.8,1399.39 5382.64,1406.23 v1(5382.64,1408.84)
ETH0_CPSW2_RST: R209.1 U42.3 U45.1 | length 2987.6
  Top Layer w5.3: U42.3@5263.64,1396.06 5264.27,1395.42 5279.02,1395.42 5398.7,1275.74 5409.26,1275.74 5432.58,1252.42 5455.3,1252.42 5509.13,1306.25 5601.19,1306.25 5662.71,1367.76 5947.06,1367.76 6006.75,1427.45 v1(6006.75,1428.12) ; U45.1@6334.74,375.59 6334.74,415.49 6343.25,424 R209.1@6366.26,424 6366.26,439.69 6407.5,480.92 6513.13,480.92 6557.54,436.51 6740.88,436.51 6830.41,526.04 6830.41,966.04 v1(6664.63,1131.82)
  SIG 1 w5.3: v1(6006.75,1428.12) 6032.1,1402.77 6443.82,1402.77 6664.63,1181.97 v1(6664.63,1131.82)
ETH1_CPSW1_RST: R221.1 U42.4 U47.1 | length 2039.5
  Top Layer w5.3: U42.4@5263.64,1415.74 5265.71,1413.67 5276.31,1413.67 5398.57,1291.41 5479.72,1291.41 5504.86,1316.55 5596.93,1316.55 5658.44,1378.06 5907.54,1378.06 v1(5937.57,1408.09) ; U47.1@6918.86,1628.95 6978.87,1628.95 R221.1@6980.08,1630.16 v1(7009.05,1630.16)
  SIG 1 w5.3: v1(5937.57,1408.09) 5937.57,1427.95 5986.52,1476.9 6445.66,1476.9 6598.92,1630.16 v1(7009.05,1630.16)
ETH1_EEPROM_A0: J21.47 R231.1 | length 118.9
  Top Layer w5.3: J21.47@6751.27,-15.3 6751.27,-67.2 v1(6762.9,-78.84)
  Bottom Layer w5.3: v1@6758.34,-83.4 6760.89,-80.85 R231.1@6807.81,-80.85
ETH1_EEPROM_A2: J21.37 R235.1 | length 80.4
  Top Layer w5.3: v1@6672.53,-47.3 J21.37@6672.53,-15.3
  Top Layer w8: v1(6672.19,-47.64) v1@6672.53,-47.3
  Bottom Layer w5.3: R235.1@6666.01,-2.31 6672.19,-8.49 v1(6672.19,-47.64)
ETH2_EEPROM_A0: J23.47 R238.2 | length 153.4
  Top Layer w5.3: J23.47@6511.2,2015.13 6511.2,1983.74 6526.72,1968.23 6568.74,1968.23 v1(6585.33,1951.64)
  Bottom Layer w5.3: v1(6585.33,1951.64) 6585.42,1951.55 R238.2@6585.42,1917.08
ETH2_EEPROM_A2: J23.37 R236.1 | length 112.5
  Top Layer w5.3: J23.37@6589.94,2015.13 6589.94,1986.59 v1(6625.88,1950.65)
  Bottom Layer w5.3: v1(6625.88,1950.65) 6633.77,1958.54 R236.1@6655.79,1958.54
EX_OSPI1_CLK: J22.10 R245.2 | length 414.2
  Top Layer w5.3: v1(6608,686) 6633.13,660.87 J22.10@6633.13,638.4
  SIG 1 w4.75: v1(6407.29,918.98) 6407.29,859.52 6580.81,686 v1(6608,686)
  Bottom Layer w5.3: R245.2@6383.42,919.69 6406.58,919.69 v1(6407.29,918.98)
EX_OSPI1_CSN0: J22.7 R243.2 | length 640.8
  Top Layer w5.3: v1(6635.54,824.27) 6648.88,810.93 J22.7@6648.88,759.66
  SIG 1 w4.75: v1(6410.25,1007.84) 6451.16,1007.84 6533.73,925.27 6533.73,762.14 6546.2,749.68 6653.82,749.68 6660,755.86 6660,816.73 6652.46,824.27 v1(6635.54,824.27)
  Bottom Layer w5.3: R243.2@6383.08,1007.26 6409.67,1007.26 v1(6410.25,1007.84)
EX_OSPI1_CSN1: J22.8
EX_OSPI1_D0: J22.14 R286.2 | length 1583.4
  Top Layer w5.3: v1(5714.39,647.95) 5930.95,647.95 5944.93,661.93 5944.93,844.92 6068.92,968.9 6103.9,968.9 6128.62,993.62 6223.95,993.62 6269.92,947.65 6284.84,932.72 6284.84,787.19 6369,703.03 6369,675.18 6437.28,606.9 6592.28,606.9 6601.63,616.25 J22.14@6601.63,638.4
  Bottom Layer w5.3: R286.2@5560.51,638.11 5704.55,638.11 v1(5714.39,647.95)
EX_OSPI1_D1: J22.15 R276.2 | length 1505.9
  Top Layer w5.3: v1(6369.13,780.23) 6369.13,839.36 6383.08,853.31 6383.08,891.22 6390.23,898.37 6413.05,898.37 6431.29,916.61 6472.78,916.61 6495.83,893.56 6495.83,836.92 6486.78,827.87 6427.12,827.87 6411.66,812.41 6411.66,728.51 6418.57,721.6 6573.88,721.6 6585.89,733.61 J22.15@6585.89,759.66
  Bottom Layer w5.3: R276.2@5664.58,702.58 5720.91,702.58 5787.88,635.61 6069.61,635.61 6103.15,669.15 6103.15,696.09 6103.15,702.9 6179.56,779.3 6182.2,781.94 6367.41,781.94 v1(6369.13,780.23)
EX_OSPI1_D2: J22.16 R289.2 | length 1626.8
  Top Layer w5.3: v1(5672.45,737.41) 5673.64,736.23 5673.64,725.23 5725.32,673.55 5829.38,673.55 5928.51,772.68 5928.51,844.57 6068.66,984.72 6093.54,984.72 6167.83,1059 6276.75,1059 6355.73,980.02 6355.73,872.33 6323.72,840.32 6323.72,796.61 6410.03,710.3 6577.4,710.3 6588.34,699.36 6588.34,677.31 6588.53,677.12 6588.53,661.67 6585.89,659.02 J22.16@6585.89,638.4
  Bottom Layer w5.3: R289.2@5560.34,736.65 5671.7,736.65 v1(5672.45,737.41)
EX_OSPI1_D3: J22.17 R277.2 | length 1519.3
  Top Layer w5.3: v1(6343.71,811.42) 6343.71,835.38 6370.54,862.21 6370.54,913.54 6396.05,939.05 6468.85,939.05 6507.48,900.42 6507.48,832.99 6491.08,816.59 6433.09,816.59 6422.66,806.16 6422.66,755.99 6446.46,732.2 6563.2,732.2 6570.14,739.14 J22.17@6570.14,759.66
  Bottom Layer w5.3: R277.2@5660.64,805.69 5660.64,786.91 5801.65,645.91 6064.91,645.91 6092.85,673.85 6092.85,704.66 6092.85,707.16 6175.29,789.6 6177.93,792.24 6324.53,792.24 v1(6343.71,811.42)
EX_OSPI1_D4: J22.19 R287.2 | length 1605.1
  Top Layer w5.3: v1(5686.11,864.75) 5667.86,883 5667.86,1073.67 5679.85,1085.66 5921.22,1085.66 5986.24,1020.64 6090.46,1020.64 6180.23,1110.41 6459.5,1110.41 6554.39,1015.52 J22.19@6554.39,759.66
  Bottom Layer w5.3: R287.2@5560.51,837.39 5660.25,837.39 5686.11,863.25 v1(5686.11,864.75)
EX_OSPI1_D5: J22.20 R278.2 | length 1520.4
  Top Layer w5.3: v1(6168.23,1013.42) 6169.51,1014.7 6169.51,1025.51 6187,1043 6276,1043 6342,977 6342,883.16 6310,851.16 6310,792.01 6404.72,697.29 6534.88,697.29 6548.94,683.23 6548.94,662.72 6553.1,658.56 6553.1,639.69 J22.20@6554.39,638.4
  Bottom Layer w5.3: R278.2@5660.64,903.91 5725.28,903.91 5739.49,918.11 5739.49,1052.74 5793.75,1107 6064.91,1107 6114,1057.91 6114,1003 6128,989 6160.28,989 6168.2,996.91 v1(6168.23,1013.42)
EX_OSPI1_D6: J22.21 R290.2 | length 1602.3
  Top Layer w5.3: v1(5689.09,972.46) 5689.09,1063.15 5699.9,1073.96 5913.89,1073.96 5980.4,1007.45 6099.31,1007.45 6189.85,1098 6378.92,1098 6405,1071.92 6480.88,1071.92 6538.64,1014.17 J22.21@6538.64,759.66
  Bottom Layer w5.3: R290.2@5560.34,937.41 5715.41,937.41 5729.19,951.19 5729.19,1003.81 5723,1010 5696,1010 5689.09,1003.09 v1(5689.09,972.46)
EX_OSPI1_D7: J22.22 R279.2 | length 1489.1
  Top Layer w5.3: v1(6207.67,1013.42) 6222.93,1028.68 6260.83,1028.68 6295.35,994.16 6295.35,791.67 6407.02,680 6523.21,680 6538.64,664.57 J22.22@6538.64,638.4
  Bottom Layer w5.3: R279.2@5660.64,1011.62 5678.62,1011.62 5788,1121 6065.9,1121 6138.46,1048.44 6249.56,1048.44 6278.92,1019.08 6278.92,982.59 6265.93,969.6 6218.82,969.6 6207.67,980.75 v1(6207.67,1013.42)
EX_OSPI1_DQS_R: J22.12 R288.2 | length 1591
  Top Layer w5.3: v1(5588.38,1048.21) 5628.5,1008.08 5628.5,742.93 5677,694.43 5677,658.97 5706.67,629.3 ; 5706.7,629.3 5707.57,628.43 6044.82,628.43 6186.59,770.21 6286.84,770.21 6356,701.04 6356,671 6430.4,596.6 6600.6,596.6 6617.38,613.38 J22.12@6617.38,638.4
  Bottom Layer w5.3: R288.2@5560.51,1038.57 5578.75,1038.57 v1(5588.38,1048.21)
EX_OSPI1_ECC_FAIL: J22.6 R244.2 | length 616.3
  Top Layer w5.3: v1(6643.94,677.87) 6664.63,657.18 J22.6@6664.63,638.4
  SIG 1 w4.75: v1(6418.93,1091.76) 6418.93,1074.99 6674.47,819.46 6674.47,708.4 v1(6643.94,677.87)
  Bottom Layer w5.3: R244.2@6383.08,1091.76 v1(6418.93,1091.76)
EX_OSPI1_RSTn: J22.5 R241.2 | length 548.2
  Top Layer w5.3: v1(6651.32,871.42) 6664.63,858.12 6664.63,792.15 J22.5@6664.63,759.66
  SIG 1 w4.75: v1(6383.42,1161.63) 6651.32,893.73 v1(6651.32,871.42)
  Bottom Layer w5.3: v1(6383.42,1161.63) 6383.89,1162.1 R241.2@6383.89,1191.18
EXT1_VMON2: J21.2 TP45.1 | length 76.4
  Top Layer w5.3: TP45.1@6357.03,154.49 6389.06,122.46 J21.2@6389.06,91.39
EXT2_VMON2: J23.2 TP54.1 | length 65.6
  Top Layer w5.3: J23.2@6873.41,1908.44 6873.41,1883.87 TP54.1@6902.41,1854.87
FB_B1: R343.1 U28.5 | length 64.2
  Top Layer w10: v1(3330.81,480.15) 3336.27,474.7 U28.5@3336.27,446.5
  Bottom Layer w10: R343.1@3329.24,507.77 3329.24,481.72 v1(3330.81,480.15)
FB_B2: R338.1 U28.20 | length 226.6
  Top Layer w5.3: U28.20@3420.91,342.17 3452.95,342.17 v1(3453.35,341.77)
  Bottom Layer w10: v1(3453.35,341.77) 3412.75,301.16 3412.75,234.05 3432.7,214.09 R338.1@3473.95,214.09
FB_B3: R349.1 U28.12 | length 180.1
  Top Layer w5.3: v1(3251.53,327.08) 3256.3,327.08 3271.39,342.17 U28.12@3290.99,342.17
  Bottom Layer w10: R349.1@3144.53,277.25 3144.53,282.22 3194.07,331.76 3240.34,331.76 3246.85,331.76 v1(3251.53,327.08)
FB_VDD_XDS3V3: C13.2 R7.1 R10.2 U4.5 | length 312.9
  Top Layer w5.3: U4.5@357.08,903.44 357.08,924.16 365.69,932.78 467.61,932.78 485.03,950.19 C13.2@485.03,974.76 481.97,977.82 R7.1@481.97,1041.61 540.03,1041.61 R10.2@541.97,1043.54
FSI_EQEP_MUX_SEL: R274.1 R275.2 U42.9 U43.1 | length 1189.2
  Top Layer w5.3: U42.9@5153.4,1415.74 5136.44,1415.74 5131.51,1420.67 5131.51,1448.26 5178.54,1495.29 5284.96,1495.29 5341.28,1438.97 5341.28,1400.77 5419.45,1322.6 5466.38,1322.6 5491.23,1347.45 5584.13,1347.45 5645.64,1408.96 5815.87,1408.96 v1(5830.57,1423.66) ; U43.1@5692.24,1339.06 5730.81,1339.06 5739.84,1330.03 v1(5740.27,1330.03)
  Bottom Layer w5.3: R275.2@5676.49,1291.82 R274.1@5737.89,1291.82 5740.27,1294.2 v1(5740.27,1330.03) 5830.57,1420.33 v1(5830.57,1423.66)
FSIRX0_C: J11.1 U25.20 | length 674.8
  Top Layer w5.3: U25.20@2914.32,1578.6 2878.39,1578.6 2816.1,1640.89 2816.1,1720.74 2874.34,1778.97 3050.51,1778.97 3061.2,1789.66 3243.83,1789.66 J11.1@3254.17,1800
FSIRX0_CLK: U25.1 U43.2 | length 6335.4
  Top Layer w5.3: v1(2791.54,858.68) 2832.54,858.68 2931.7,759.52 2931.7,715.44 2988.32,658.82 2988.32,379.71 3015.85,352.17 3015.85,270.83 3196.43,90.24 3196.43,-35.03 3216.77,-55.36 3630.59,-55.36 3698.88,12.92 3702.21,16.25 3847.27,16.25 3850.6,12.92 3907.21,-43.69 4523.31,-43.69 4540.96,-26.04 5222.8,-26.04 5457.96,209.12 5869.35,209.12 5897.99,237.76 5897.99,438.01 5794.33,541.67 5643.98,541.67 5457.65,728 5457.65,861.35 5439.06,879.94 5439.06,1000.62 5446.05,1007.61 5446.05,1072.66 5421.57,1097.14 5421.57,1164.96 5436.56,1179.95 5470.46,1179.95 5517.15,1226.64 5517.15,1260.02 5542.77,1285.65 5630.37,1285.65 5658.19,1313.47 U43.2@5692.24,1313.47 ; v1(2892.39,1108.79) 2892.39,1112.22 2897.03,1116.87 2897.03,1117.51 2919.63,1140.1 2919.63,1309.38 2907.72,1321.29 2907.19,1321.29 2836.62,1391.86 2836.62,1472.46 2883.7,1519.54 U25.1@2914.32,1519.54
  Bottom Layer w5.3: v1(2791.54,858.68) 2791.54,934.54 2892.39,1035.39 v1(2892.39,1108.79)
FSIRX0_D0: J11.5 U25.18 | length 665.4
  Top Layer w5.3: U25.18@2949.76,1614.03 2949.76,1642.4 3066.07,1758.7 3293.34,1758.7 3309.63,1774.99 3309.63,1825.95 3328.96,1845.28 3408.89,1845.28 J11.5@3454.17,1800
FSIRX0_D1: J11.7 U25.17 | length 676.3
  Top Layer w5.3: U25.17@2969.44,1614.03 2969.44,1638.81 3078.66,1748.02 3273.19,1748.02 3299.59,1748.02 3300.91,1749.35 3309.97,1758.41 3312.23,1758.41 3512.58,1758.41 J11.7@3554.17,1800
FSIRX0_DATA0: U25.3 U43.5 | length 6173.3
  Top Layer w5.3: v1(2754.96,799.79) 2773.66,818.48 2851.24,818.48 2917.88,751.85 2917.88,657.1 2976.74,598.24 2976.74,376.72 3005.55,347.91 3005.55,266.56 3186.13,85.98 3186.13,-40.78 3213.56,-68.2 3633.11,-68.2 3707.27,5.95 3843.01,5.95 3902.95,-53.99 4529.72,-53.99 4547.36,-36.34 5229.35,-36.34 5464.46,198.77 5873.56,198.77 5908.93,234.13 5908.93,446.07 5799.33,555.67 5660.61,555.67 5518.32,697.96 5518.32,1186.38 5568.64,1236.7 U43.5@5692.24,1236.7 ; v1(2929.87,1105.56) 2930.43,1106.11 2930.43,1129.81 2930.23,1130.01 2930.23,1332.49 2930.46,1332.72 2930.46,1348.9 2930.23,1349.13 2930.23,1391.11 2949.76,1410.64 U25.3@2949.76,1484.11
  Bottom Layer w5.3: v1(2754.96,799.79) 2757.39,802.22 2764.87,802.22 2827.86,865.21 2827.86,940.38 2932.86,1045.38 2932.86,1096.1 2932.3,1096.66 2932.3,1103.13 v1(2929.87,1105.56)
FSIRX0_DATA1: U25.4 U43.11 | length 6252
  Top Layer w5.3: v1(2796.71,795.12) 2796.71,752.67 2960.23,589.15 2960.23,376.53 2995.25,341.52 2995.25,262.29 3174.36,83.19 3174.36,-46.12 3210.35,-82.11 3634.77,-82.11 3712.53,-4.35 3837.41,-4.35 3918.53,-85.47 5199.92,-85.47 5471.82,186.43 5885.4,186.43 5919.23,220.26 5919.23,453.77 5803.71,569.29 5670.69,569.29 5596.59,643.39 5596.59,802.77 5546.86,852.51 5546.86,1093.59 5585.09,1131.82 5640.53,1131.82 5645.94,1137.24 5701.17,1137.24 5797.12,1137.24 5870.99,1211.11 U43.11@5916.65,1211.11 ; v1(2962.07,1122.12) 2940.83,1143.36 2940.83,1386.72 2969.44,1415.34 U25.4@2969.44,1484.11
  Bottom Layer w5.3: v1(2796.71,795.12) 2847.33,845.74 2847.33,926.56 2962.07,1041.3 v1(2962.07,1122.12)
FSITX0_C: J11.2 U25.16 | length 1115.5
  Top Layer w5.3: U25.16@2989.13,1614.03 2989.13,1637.33 3089.52,1737.72 3277.46,1737.72 3303.86,1737.72 3314.24,1748.11 3566.9,1748.11 3598.65,1779.85 3598.65,1824.84 3578.43,1845.05 3438.33,1845.05 3424.41,1858.97 3338.56,1858.97 3290.03,1858.97 3254.17,1894.83 J11.2@3254.17,1900
FSITX0_D0: J11.6 U25.15 | length 918.8
  Top Layer w5.3: U25.15@3008.81,1614.03 3008.81,1636.2 3100.04,1727.42 3281.72,1727.42 3311.23,1727.42 3321.62,1737.81 3477.76,1737.81 3571.17,1737.81 3572.41,1739.05 3606.42,1773.05 3608.95,1775.58 3608.95,1831.05 3584.65,1855.35 3498.82,1855.35 J11.6@3454.17,1900
FSITX0_D1: J11.8 U25.14 | length 965.4
  Top Layer w5.3: U25.14@3028.5,1614.03 3028.5,1635.16 3110.46,1717.12 3315.92,1717.12 3326.31,1727.51 3482.02,1727.51 3575.44,1727.51 3576.08,1728.15 3603.14,1755.21 3666.03,1755.21 3694.23,1783.41 3694.23,1832.6 3674.59,1852.24 3623.27,1852.24 3575.51,1900 J11.8@3554.17,1900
